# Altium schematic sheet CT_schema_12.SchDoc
size 147 x 119 mm
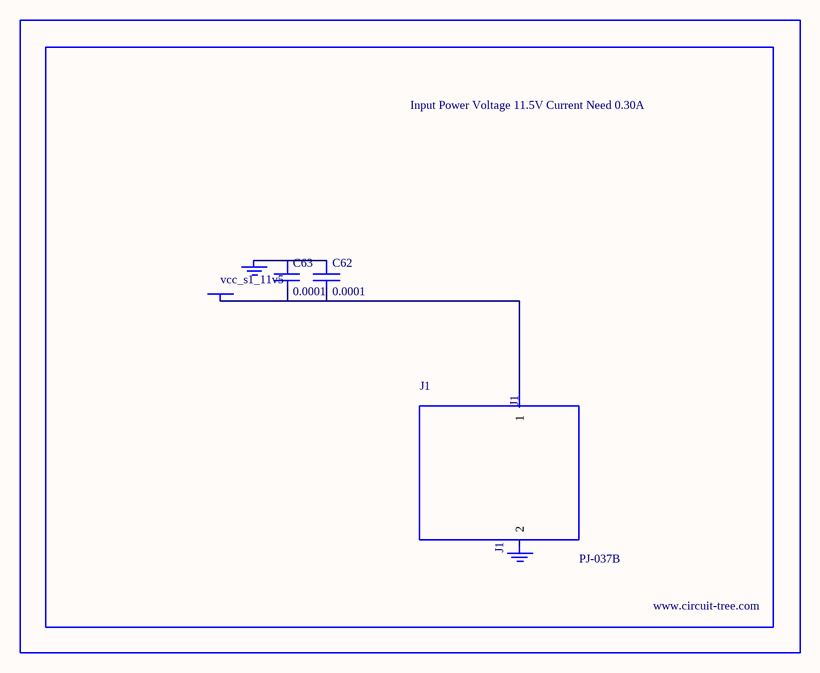
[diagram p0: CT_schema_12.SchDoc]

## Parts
BORDER11  (no value)
C62  0.0001  [EXV-9H]
C63  0.0001  [EXV-9H]
GND_INSTANCE_11_0  (no value)
GND_INSTANCE_11_1  (no value)
J1  PJ-037B  [PJ-037B_PACKAGE]
POWER_INSTANCE_11_0  vcc_s1_11v5

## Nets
NetC62_1: C62.1 C63.1 GND_INSTANCE_11_0.0(GND)
NetC62_2: C62.2 C63.2 J1.1 POWER_INSTANCE_11_0.0(PWR)

Not connected (* = marked no-connect by the designer): GND_INSTANCE_11_1 0(GND); J1 2

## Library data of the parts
BORDER11 = BORDER_PAGE11
C62 C63 = EDK107M035A9HAA
GND_INSTANCE_11_0 GND_INSTANCE_11_1 = GND
POWER_INSTANCE_11_0 = PWR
